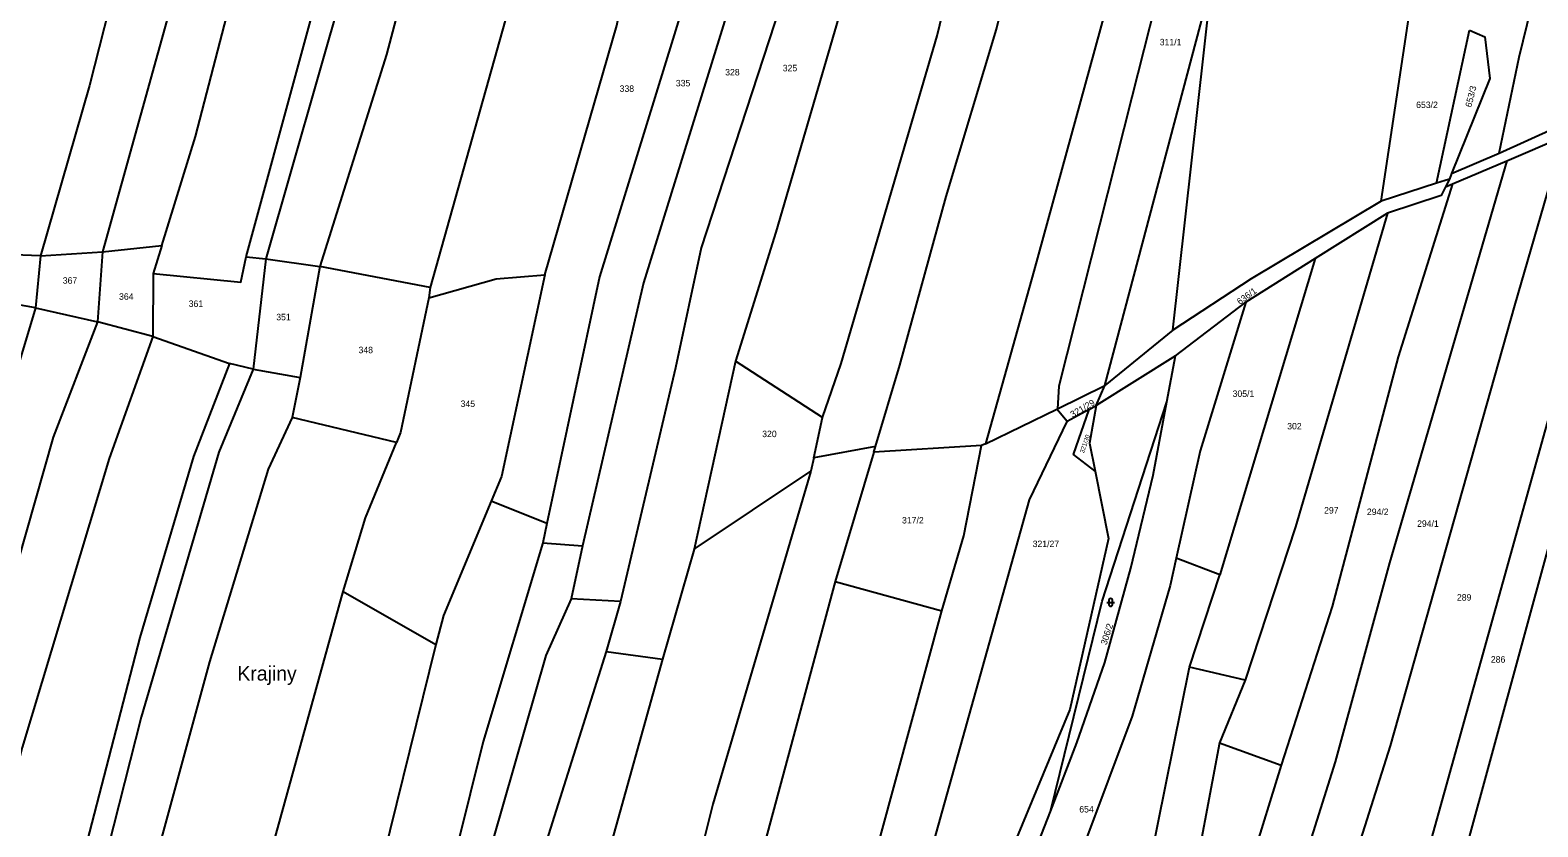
# Model space of a CAD drawing. Extents: x -744566 to -741843, y -1128407 to -1126744.
# Drawn here: x -743655.8 to -743260.5, y -1127888.2 to -1127679.3 of the extents above; entities that cross this region are included whole.
import ezdxf

# ---------------------------------------------------------------- set-up
doc = ezdxf.new("R2010")
doc.units = 0
for name, color, linetype in [('Hranice parcel', 7, 'Continuous'), ('Parcelní čísla', 7, 'Continuous'), ('Pop  PČ popisy', 7, 'Continuous'), ('Vnitřní kresba', 7, 'Continuous'), ('Značky kultur', 7, 'Continuous')]:
    doc.layers.add(name, color=color, linetype=linetype)

msp = doc.modelspace()

# ---------------------------------------------------------------- linework, layer by layer
at = {"layer": 'Hranice parcel'}
for p, q in [((-743301.55, -1127724.14), (-743293.8, -1127672.4)), ((-743287.1, -1127719.44), (-743278.45, -1127679.23)), ((-743270.64, -1127711.51), (-743255.66, -1127704.74)), ((-743268.66, -1127713.55), (-743253.81, -1127707.15)), ((-743283.11, -1127716.84), (-743270.64, -1127711.51)), ((-743282.88, -1127719.56), (-743268.66, -1127713.55)), ((-743283.11, -1127716.84), (-743283.71, -1127718.34)), ((-743287.1, -1127719.44), (-743301.55, -1127724.14)), ((-743283.71, -1127718.34), (-743287.1, -1127719.44)), ((-743283.71, -1127718.34), (-743284.74, -1127720.35)), ((-743284.74, -1127720.35), (-743282.88, -1127719.56)), ((-743299.93, -1127727.23), (-743318.89, -1127739.14)), ((-743653.09, -1127738.43), (-743673.66, -1127737.68)), ((-743653.09, -1127738.43), (-743636.86, -1127737.44)), ((-743636.86, -1127737.44), (-743638.13, -1127755.73)), ((-743636.86, -1127737.44), (-743621.23, -1127735.75)), ((-743621.23, -1127735.75), (-743623.51, -1127743.05)), ((-743653.09, -1127738.43), (-743654.42, -1127752.06)), ((-743599.16, -1127738.75), (-743594.04, -1127739.28)), ((-743594.04, -1127739.28), (-743597.33, -1127768.16)), ((-743594.04, -1127739.28), (-743579.85, -1127741.23)), ((-743579.85, -1127741.23), (-743585.04, -1127770.39)), ((-743550.89, -1127746.78), (-743579.85, -1127741.23)), ((-743318.89, -1127739.14), (-743343.93, -1127822.1)), ((-743318.89, -1127739.14), (-743337.1, -1127750.58)), ((-743623.51, -1127743.05), (-743623.67, -1127759.6)), ((-743654.42, -1127752.06), (-743674.43, -1127748.6)), ((-743550.89, -1127746.78), (-743551.29, -1127749.44)), ((-743654.42, -1127752.06), (-743638.13, -1127755.73)), ((-743355.5, -1127764.66), (-743337.1, -1127750.58)), ((-743623.67, -1127759.6), (-743638.13, -1127755.73)), ((-743623.67, -1127759.6), (-743603.54, -1127766.74)), ((-743355.5, -1127764.66), (-743376.33, -1127777.73)), ((-743357.75, -1127776.76), (-743355.5, -1127764.66)), ((-743597.33, -1127768.16), (-743603.54, -1127766.74)), ((-743597.33, -1127768.16), (-743585.04, -1127770.39)), ((-743470.88, -1127766.12), (-743481.69, -1127815.4)), ((-743448.1, -1127780.84), (-743470.88, -1127766.12)), ((-743585.04, -1127770.39), (-743587.1, -1127780.87)), ((-743386.45, -1127778.59), (-743374.07, -1127772.46)), ((-743376.33, -1127777.73), (-743374.07, -1127772.46)), ((-743559.77, -1127787.4), (-743587.1, -1127780.87)), ((-743450.34, -1127791.41), (-743448.1, -1127780.84)), ((-743405.3, -1127787.74), (-743386.64, -1127778.68)), ((-743386.64, -1127778.68), (-743386.45, -1127778.59)), ((-743383.94, -1127781.89), (-743386.64, -1127778.68)), ((-743378.18, -1127778.74), (-743383.94, -1127781.89)), ((-743378.18, -1127778.74), (-743376.33, -1127777.73)), ((-743434.17, -1127788.45), (-743450.34, -1127791.41)), ((-743406.34, -1127788.25), (-743434.62, -1127789.95)), ((-743434.62, -1127789.95), (-743434.17, -1127788.45)), ((-743405.3, -1127787.74), (-743406.34, -1127788.25)), ((-743450.34, -1127791.41), (-743451.09, -1127794.94)), ((-743434.62, -1127789.95), (-743444.74, -1127823.92)), ((-743481.69, -1127815.4), (-743451.09, -1127794.94)), ((-743520.33, -1127808.71), (-743534.94, -1127802.78)), ((-743520.33, -1127808.71), (-743521.42, -1127813.7)), ((-743521.42, -1127813.7), (-743511, -1127814.57)), ((-743511, -1127814.57), (-743513.93, -1127828.42)), ((-743481.69, -1127815.4), (-743490.01, -1127844.27)), ((-743343.93, -1127822.1), (-743355.31, -1127817.79)), ((-743444.74, -1127823.92), (-743416.75, -1127831.61)), ((-743351.87, -1127846.33), (-743343.93, -1127822.1)), ((-743573.69, -1127826.51), (-743549.4, -1127840.4)), ((-743500.98, -1127829.09), (-743513.93, -1127828.42)), ((-743500.98, -1127829.09), (-743504.76, -1127842.24)), ((-743490.01, -1127844.27), (-743533.73, -1128001.44)), ((-743504.76, -1127842.24), (-743490.01, -1127844.27)), ((-743337.26, -1127849.72), (-743351.87, -1127846.33)), ((-743337.26, -1127849.72), (-743344, -1127866.17)), ((-743344, -1127866.17), (-743327.83, -1127872.04)), ((-743327.83, -1127872.04), (-743336.15, -1127899.16))]:
    msp.add_line(p, q, dxfattribs=at)
for points in [[(-743566.53, -1127412.16), (-743578.37, -1127448.95), (-743606.94, -1127562.76), (-743640.25, -1127693.79), (-743653.09, -1127738.43)], [(-743551.54, -1127422.32), (-743561.28, -1127447), (-743590.72, -1127561.84), (-743612.33, -1127649.25), (-743636.86, -1127737.44)], [(-743621.23, -1127735.75), (-743612.44, -1127707.12), (-743584.91, -1127601.01), (-743579.58, -1127574.43), (-743546.31, -1127450.09), (-743538.8, -1127430.57)], [(-743599.16, -1127738.75), (-743570.37, -1127633.12), (-743554.73, -1127564.38), (-743526.58, -1127459.91), (-743519.14, -1127443.31)], [(-743514.57, -1127446.27), (-743521.89, -1127463.56), (-743545.21, -1127553.77), (-743561.74, -1127621.6), (-743573.61, -1127667.99), (-743594.04, -1127739.28)], [(-743498.56, -1127456.64), (-743508.94, -1127484.15), (-743529.52, -1127550.64), (-743545.56, -1127622.11), (-743562.33, -1127685.66), (-743579.85, -1127741.23)], [(-743448.1, -1127780.84), (-743443.18, -1127766.73), (-743418.02, -1127680.71), (-743407.6, -1127637.74), (-743395.56, -1127586.74), (-743381.16, -1127539.8), (-743369.67, -1127509.02)], [(-743434.17, -1127788.45), (-743427.78, -1127767.16), (-743415.63, -1127722.89), (-743402.41, -1127679.01), (-743378.99, -1127584.19), (-743364.14, -1127538.04), (-743355.14, -1127514.62)], [(-743337.56, -1127551.48), (-743342.72, -1127565.43), (-743360.58, -1127625.49), (-743392.64, -1127742.44), (-743405.3, -1127787.74)], [(-743270.64, -1127711.51), (-743265.43, -1127686.37), (-743248.78, -1127618.41), (-743240.66, -1127598.71), (-743230.04, -1127580.88)], [(-743512.98, -1127598.18), (-743531.28, -1127676.73), (-743550.89, -1127746.78)], [(-743339.88, -1127602.23), (-743346.97, -1127624.14), (-743357.58, -1127659.83), (-743366.95, -1127696.84), (-743386.06, -1127772.64), (-743386.45, -1127778.59)], [(-743374.07, -1127772.46), (-743345.92, -1127666.2), (-743341.91, -1127628.76), (-743339.88, -1127602.23)], [(-743520.82, -1127743.45), (-743502.02, -1127678), (-743491.75, -1127625.57)], [(-743475.93, -1127632.96), (-743482.22, -1127665.09), (-743506.51, -1127743.94), (-743520.33, -1127808.71)], [(-743466.39, -1127642.3), (-743469.86, -1127664.22), (-743494.95, -1127745.55), (-743511, -1127814.57)], [(-743453.46, -1127642.28), (-743456.19, -1127663.78), (-743479.83, -1127736.34), (-743486.56, -1127767.82), (-743500.98, -1127829.09)], [(-743438.1, -1127642.54), (-743439.27, -1127647.07), (-743435.59, -1127647.51), (-743460.31, -1127732.22), (-743470.88, -1127766.12)], [(-743278.45, -1127679.23), (-743274.37, -1127681.04), (-743273.1, -1127691.93), (-743283.11, -1127716.84)], [(-743225.59, -1127692.63), (-743249.75, -1127785.46), (-743287.33, -1127923.2), (-743297.04, -1127954.42)], [(-743235.82, -1127698.28), (-743249, -1127749.54), (-743300.05, -1127932.95), (-743303.92, -1127943.26)], [(-743253.81, -1127707.15), (-743266.62, -1127751.47), (-743299.27, -1127867.01), (-743314.24, -1127914.43)], [(-743268.66, -1127713.55), (-743299.42, -1127819.01), (-743313.64, -1127871.22), (-743325.19, -1127907.9)], [(-743282.88, -1127719.56), (-743297.14, -1127764.91), (-743314.44, -1127830.42), (-743327.83, -1127872.04)], [(-743284.74, -1127720.35), (-743285.9, -1127722.61), (-743299.93, -1127727.23)], [(-743301.55, -1127724.14), (-743335.67, -1127744.51), (-743356.23, -1127757.98), (-743374.07, -1127772.46)], [(-743299.93, -1127727.23), (-743324.05, -1127809.53), (-743337.26, -1127849.72)], [(-743623.51, -1127743.05), (-743600.59, -1127745.39), (-743599.16, -1127738.75)], [(-743551.29, -1127749.44), (-743533.58, -1127744.49), (-743520.82, -1127743.45)], [(-743520.82, -1127743.45), (-743532.26, -1127796.34), (-743534.94, -1127802.78)], [(-743551.29, -1127749.44), (-743558.72, -1127784.83), (-743559.77, -1127787.4)], [(-743654.42, -1127752.06), (-743678.95, -1127833.74), (-743701.86, -1127917.81), (-743716.39, -1127977.76), (-743727.47, -1128007.97)], [(-743337.1, -1127750.58), (-743349.06, -1127789.63), (-743355.31, -1127817.79)], [(-743638.13, -1127755.73), (-743649.76, -1127786.02), (-743663.84, -1127835.21), (-743701.08, -1127980.88), (-743710.41, -1128008.62)], [(-743623.67, -1127759.6), (-743635.09, -1127791.61), (-743657.85, -1127867.39), (-743686.5, -1127979.4), (-743693.63, -1128000.15)], [(-743603.54, -1127766.74), (-743612.96, -1127791.11), (-743627.05, -1127838.6), (-743649.69, -1127926.04), (-743667.73, -1127984.22)], [(-743597.33, -1127768.16), (-743606.36, -1127789.97), (-743626.72, -1127859.49), (-743638.35, -1127905.26), (-743659.84, -1127983.12)], [(-743388.31, -1127884.17), (-743374.7, -1127829.05), (-743357.75, -1127776.76)], [(-743388.31, -1127884.17), (-743381.41, -1127866.19), (-743374.06, -1127845.14), (-743367.18, -1127820.36), (-743361.33, -1127795.97), (-743357.75, -1127776.76)], [(-743587.1, -1127780.87), (-743593.35, -1127794.42), (-743608.73, -1127844.98), (-743637.18, -1127949.14), (-743646.98, -1127982.69)], [(-743376.61, -1127794.9), (-743382.22, -1127790.53), (-743378.18, -1127778.74)], [(-743376.33, -1127777.73), (-743378.06, -1127787.61), (-743376.61, -1127794.9)], [(-743440.39, -1127970.17), (-743422.4, -1127904.63), (-743393.77, -1127802.48), (-743383.94, -1127781.89)], [(-743573.69, -1127826.51), (-743567.83, -1127807.19), (-743559.77, -1127787.4)], [(-743416.75, -1127831.61), (-743411.02, -1127811.93), (-743406.34, -1127788.25)], [(-743451.09, -1127794.94), (-743476.79, -1127882.29), (-743506.61, -1128001.51)], [(-743376.61, -1127794.9), (-743373.1, -1127812.6), (-743383.25, -1127857.46), (-743405.64, -1127911.7), (-743425.47, -1127948.11), (-743440.39, -1127970.17)], [(-743534.94, -1127802.78), (-743547.45, -1127832.8), (-743549.4, -1127840.4)], [(-743521.42, -1127813.7), (-743536.99, -1127865.85), (-743543.84, -1127893.3), (-743572.96, -1128001.22)], [(-743355.31, -1127817.79), (-743356.91, -1127824.97), (-743366.89, -1127859.22), (-743379.33, -1127892.58), (-743393.74, -1127924.28), (-743408.65, -1127951.21)], [(-743444.74, -1127823.92), (-743469.54, -1127916.07), (-743482.7, -1127966.88), (-743494.24, -1128003.18)], [(-743620.48, -1127990.48), (-743607.74, -1127949.5), (-743573.69, -1127826.51)], [(-743513.93, -1127828.42), (-743520.57, -1127843.27), (-743542.77, -1127920.67), (-743563.76, -1128002.02)], [(-743467.06, -1128006.86), (-743456.95, -1127979.38), (-743416.75, -1127831.61)], [(-743549.4, -1127840.4), (-743566.66, -1127910.22), (-743583.63, -1127970.8), (-743593.27, -1127998.19)], [(-743504.76, -1127842.24), (-743521.89, -1127896.66), (-743544.94, -1127982.71), (-743551.38, -1128002.22)], [(-743408.55, -1128037.93), (-743399.31, -1128017.21), (-743362.28, -1127897.95), (-743351.87, -1127846.33)], [(-743344, -1127866.17), (-743351.96, -1127908.52), (-743367.18, -1127962.23), (-743390, -1128032.51), (-743397.3, -1128045.42)], [(-743445.65, -1127989.32), (-743436.62, -1127977.47), (-743420.24, -1127951.33), (-743404.89, -1127922.15), (-743391.42, -1127892.28), (-743388.31, -1127884.17)]]:
    msp.add_lwpolyline(points, dxfattribs=at)
at = {"layer": 'Vnitřní kresba'}
msp.add_line((-743356.23, -1127757.98), (-743345.92, -1127666.2), dxfattribs=at)
at = {"layer": 'Značky kultur'}
for p, q in [((-743373.511, -1127829.351), (-743371.509, -1127829.351)), ((-743373.011, -1127828.851), (-743373.011, -1127829.852)), ((-743372.009, -1127829.852), (-743372.009, -1127828.851))]:
    msp.add_line(p, q, dxfattribs=at)
for centre, start, end in [((-743372.51, -1127828.851), 0, 180), ((-743372.51, -1127829.851), 180, 359.98789)]:
    msp.add_arc(centre, 0.5, start, end, dxfattribs=at)

# ---------------------------------------------------------------- texts
at = {"layer": 'Parcelní čísla'}
for s, p in [('311/1', (-743359.65, -1127683.25)), ('328', (-743473.57, -1127691.14)), ('325', (-743458.48, -1127690.06)), ('338', (-743501.25, -1127695.45)), ('335', (-743486.51, -1127694.01)), ('653/2', (-743292.41, -1127699.7)), ('367', (-743647.24, -1127745.78)), ('364', (-743632.49, -1127749.99)), ('361', (-743614.23, -1127751.87)), ('351', (-743591.27, -1127755.37)), ('348', (-743569.71, -1127764)), ('345', (-743542.94, -1127778.11)), ('305/1', (-743340.54, -1127775.48)), ('320', (-743463.87, -1127786.02)), ('302', (-743326.22, -1127783.99)), ('297', (-743316.55, -1127806.06)), ('294/2', (-743305.33, -1127806.45)), ('317/2', (-743427.21, -1127808.66)), ('294/1', (-743292.17, -1127809.55)), ('321/27', (-743392.96, -1127814.86)), ('289', (-743281.72, -1127828.9)), ('286', (-743272.83, -1127845.17)), ('654', (-743380.734, -1127884.47))]:
    msp.add_text(s, height=1.7, dxfattribs=at).set_placement(p)
for s, height, rotation, p in [('653/3', 1.7, 76, (-743277.945, -1127699.615)), ('636/1', 1.7, 36, (-743338.644, -1127751.377)), ('321/29', 1.7, 30, (-743382.475, -1127780.956)), ('321/30', 1.19, 71, (-743379.547, -1127790.353)), ('306/2', 1.7, 72, (-743373.578, -1127840.65))]:
    msp.add_text(s, height=height, rotation=rotation, dxfattribs=at).set_placement(p)
at = {"layer": 'Pop  PČ popisy'}
msp.add_text('Krajiny', height=3.8, dxfattribs=at).set_placement((-743601.45, -1127849.89))

doc.saveas('drawing.dxf')
